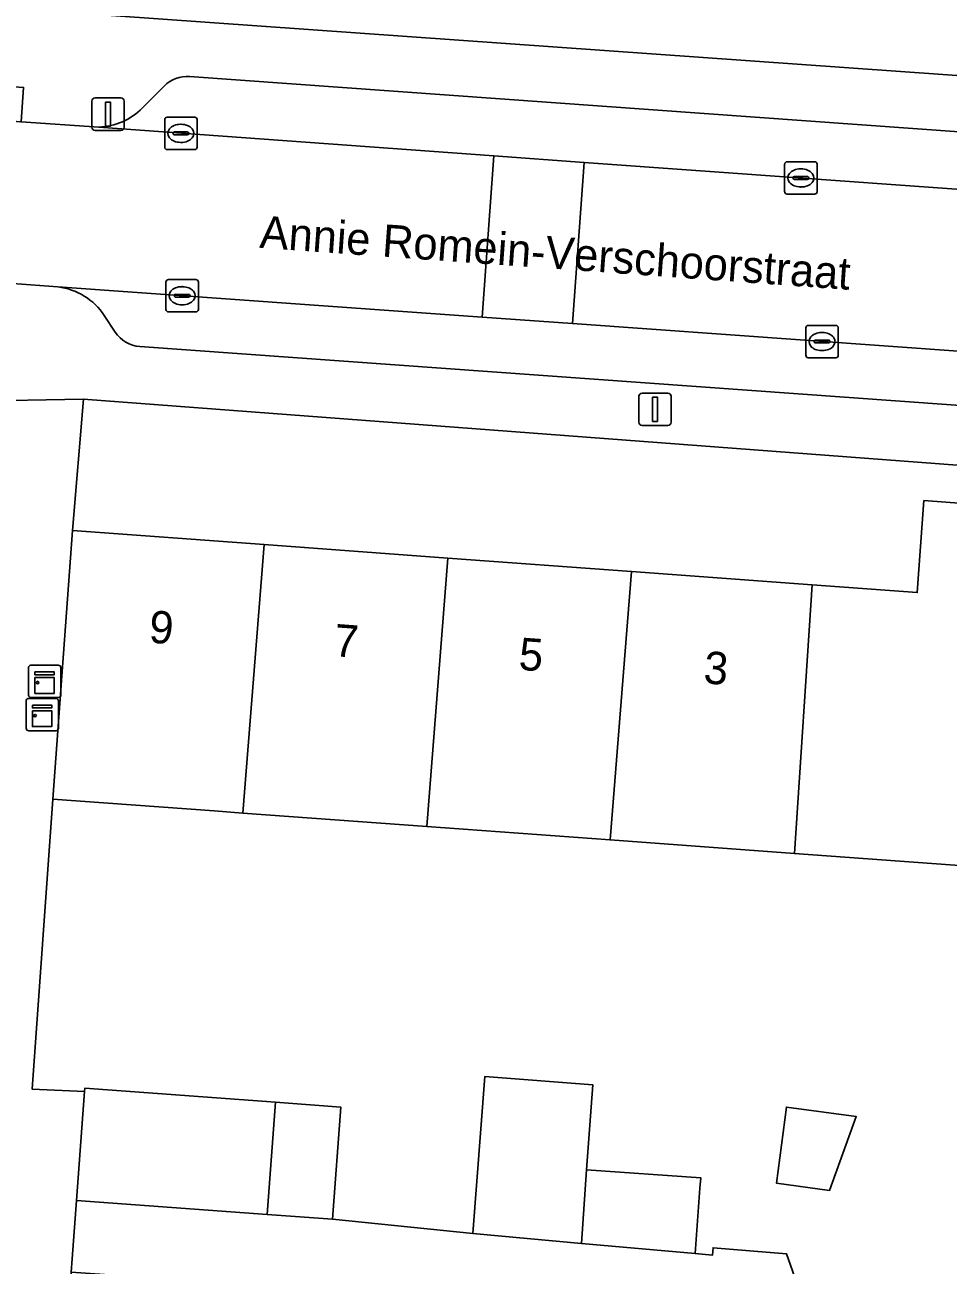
# Model space of a CAD drawing. Extents: x 160304 to 160955, y 383684 to 384161.
# Drawn here: x 160524.56 to 160553.09, y 383999.81 to 384038.14 of the extents above; entities that cross this region are included whole.
import ezdxf

# ---------------------------------------------------------------- set-up
doc = ezdxf.new("R2010")
doc.units = 0
for name, color, linetype in [('IMGEO_Erf', 7, 'Continuous'), ('IMGEO_Kast', 7, 'Continuous'), ('IMGEO_Kolk', 7, 'Continuous'), ('IMGEO_Lichtmast', 7, 'Continuous'), ('IMGEO_Muur', 7, 'Continuous'), ('IMGEO_Openbare_ruimte_label', 7, 'Continuous'), ('IMGEO_Pand', 7, 'Continuous'), ('IMGEO_Pand_nummerreeks', 7, 'Continuous'), ('IMGEO_Parkeervlak_open', 7, 'Continuous'), ('IMGEO_Rijbaan_lokaal_open', 7, 'Continuous'), ('IMGEO_Voetpad_open', 7, 'Continuous')]:
    doc.layers.add(name, color=color, linetype=linetype)

msp = doc.modelspace()

# ---------------------------------------------------------------- linework, layer by layer
at = {"layer": 'IMGEO_Erf'}
for points in [[(160575.545, 384053.821), (160571.219, 384050.086), (160566.909, 384046.364), (160559.815, 384040.236), (160550.457, 384040.871), (160544.77, 384041.284), (160539.067, 384041.697), (160533.4, 384042.108), (160527.543, 384042.533), (160527.234, 384038.426), (160562.223, 384035.951), (160577.428, 384049.127)], [(160596.174, 383986.448), (160584.428, 384000), (160576.873, 384008.716), (160576.438, 384011.974), (160567.161, 384022.807), (160563.188, 384023.793), (160526.375, 384026.574), (160526.037, 384022.511), (160531.953, 384022.076), (160537.633, 384021.659), (160543.309, 384021.242), (160548.888, 384020.833), (160552.137, 384020.594), (160552.345, 384023.437), (160555.755, 384023.187), (160558.392, 384020.13), (160564.484, 384013.069), (160568.208, 384008.753), (160571.874, 384004.582), (160574.541, 384006.884), (160578.378, 384002.452), (160580.501, 384000), (160582.098, 383998.155)], [(160554.286, 384012.093), (160548.348, 384012.529), (160542.649, 384012.948), (160536.981, 384013.365), (160531.302, 384013.782), (160530.415, 384013.847), (160525.428, 384014.213), (160524.792, 384005.245), (160526.404, 384005.17), (160526.412, 384005.276), (160532.305, 384004.843), (160534.327, 384004.694), (160534.073, 384001.224), (160538.402, 384000.781), (160538.777, 384005.639), (160542.11, 384005.382), (160541.923, 384002.758), (160545.446, 384002.508), (160545.423, 384002.185), (160545.279, 384000.164), (160545.808, 384000.116), (160545.829, 384000.347), (160548.095, 384000.159), (160549.241, 383996.917)]]:
    msp.add_lwpolyline(points, dxfattribs=at)
msp.add_lwpolyline([(160549.422, 384002.12), (160547.788, 384002.344), (160548.094, 384004.693), (160550.253, 384004.398)], close=True, dxfattribs=at)
at = {"layer": 'IMGEO_Kast'}
for p, q in [((160524.677, 384017.425), (160524.677, 384018.266)), ((160524.677, 384018.266), (160524.677, 384017.425)), ((160524.752, 384018.35), (160525.593, 384018.35)), ((160525.593, 384018.35), (160524.752, 384018.35)), ((160525.677, 384018.275), (160525.677, 384017.434)), ((160525.677, 384017.434), (160525.677, 384018.275)), ((160524.602, 384016.4), (160524.602, 384017.241)), ((160524.602, 384017.241), (160524.602, 384016.4)), ((160524.677, 384017.325), (160525.518, 384017.325)), ((160525.518, 384017.325), (160524.677, 384017.325)), ((160525.602, 384017.35), (160524.761, 384017.35)), ((160524.761, 384017.35), (160525.602, 384017.35)), ((160525.602, 384017.25), (160525.602, 384016.409)), ((160525.602, 384016.409), (160525.602, 384017.25)), ((160525.527, 384016.325), (160524.686, 384016.325)), ((160524.686, 384016.325), (160525.527, 384016.325))]:
    msp.add_line(p, q, dxfattribs=at)
for points in [[(160524.872, 384018.14), (160525.472, 384018.14), (160525.472, 384018.055), (160524.872, 384018.055), (160524.872, 384018.14)], [(160524.872, 384017.965), (160525.472, 384017.965), (160525.472, 384017.476), (160524.872, 384017.476), (160524.872, 384017.965)], [(160524.797, 384017.115), (160525.397, 384017.115), (160525.397, 384017.03), (160524.797, 384017.03), (160524.797, 384017.115)], [(160524.797, 384016.94), (160525.397, 384016.94), (160525.397, 384016.451), (160524.797, 384016.451), (160524.797, 384016.94)]]:
    msp.add_lwpolyline(points, dxfattribs=at)
for centre in [(160524.956, 384017.814), (160524.881, 384016.789)]:
    msp.add_circle(centre, 0.0377, dxfattribs=at)
for centre, start, end in [((160524.755, 384018.272), 92.4484, 184.2845), ((160524.755, 384018.272), 92.4484, 184.2845), ((160525.599, 384018.272), 2.4484, 94.2845), ((160525.599, 384018.272), 2.4484, 94.2845), ((160524.68, 384017.247), 92.4484, 184.2845), ((160524.68, 384017.247), 92.4484, 184.2845), ((160524.755, 384017.428), 182.4484, 274.2845), ((160524.755, 384017.428), 182.4484, 274.2845), ((160525.524, 384017.247), 2.4484, 94.2845), ((160525.524, 384017.247), 2.4484, 94.2845), ((160525.599, 384017.428), 272.4484, 4.2845), ((160525.599, 384017.428), 272.4484, 4.2845), ((160524.68, 384016.403), 182.4484, 274.2845), ((160524.68, 384016.403), 182.4484, 274.2845), ((160525.524, 384016.403), 272.4484, 4.2845), ((160525.524, 384016.403), 272.4484, 4.2845)]:
    msp.add_arc(centre, 0.0779, start, end, dxfattribs=at)
at = {"layer": 'IMGEO_Kolk'}
for p, q in [((160528.884, 384034.361), (160528.884, 384035.213)), ((160528.959, 384035.287), (160529.811, 384035.287)), ((160529.885, 384035.213), (160529.885, 384034.361)), ((160529.143, 384034.781), (160529.143, 384034.793)), ((160529.581, 384034.744), (160529.183, 384034.744)), ((160529.186, 384034.83), (160529.584, 384034.83)), ((160529.372, 384035.067), (160529.397, 384035.067)), ((160529.627, 384034.793), (160529.627, 384034.781)), ((160529.395, 384034.507), (160529.37, 384034.507)), ((160529.811, 384034.287), (160528.959, 384034.287)), ((160548.041, 384032.983), (160548.041, 384033.835)), ((160548.116, 384033.909), (160548.968, 384033.909)), ((160548.529, 384033.689), (160548.554, 384033.689)), ((160549.042, 384033.835), (160549.042, 384032.983)), ((160548.3, 384033.403), (160548.3, 384033.415)), ((160548.738, 384033.366), (160548.34, 384033.366)), ((160548.343, 384033.452), (160548.741, 384033.452)), ((160548.784, 384033.415), (160548.784, 384033.403)), ((160548.968, 384032.909), (160548.116, 384032.909)), ((160548.552, 384033.129), (160548.527, 384033.129)), ((160528.924, 384029.343), (160528.924, 384030.195)), ((160528.999, 384030.269), (160529.851, 384030.269)), ((160529.925, 384030.195), (160529.925, 384029.343)), ((160529.183, 384029.763), (160529.183, 384029.775)), ((160529.621, 384029.726), (160529.223, 384029.726)), ((160529.226, 384029.812), (160529.624, 384029.812)), ((160529.412, 384030.049), (160529.437, 384030.049)), ((160529.667, 384029.775), (160529.667, 384029.763)), ((160529.435, 384029.489), (160529.41, 384029.489)), ((160529.851, 384029.269), (160528.999, 384029.269)), ((160548.695, 384027.927), (160548.695, 384028.779)), ((160548.77, 384028.853), (160549.622, 384028.853)), ((160549.183, 384028.633), (160549.208, 384028.633)), ((160549.696, 384028.779), (160549.696, 384027.927)), ((160548.954, 384028.347), (160548.954, 384028.359)), ((160549.392, 384028.31), (160548.994, 384028.31)), ((160548.997, 384028.396), (160549.395, 384028.396)), ((160549.438, 384028.359), (160549.438, 384028.347)), ((160549.622, 384027.853), (160548.77, 384027.853)), ((160549.206, 384028.073), (160549.181, 384028.073))]:
    msp.add_line(p, q, dxfattribs=at)
for points in [[(160528.884, 384034.361), (160528.884, 384035.213)], [(160528.959, 384035.287), (160529.811, 384035.287)], [(160529.885, 384035.213), (160529.885, 384034.361)], [(160529.811, 384034.287), (160528.959, 384034.287)], [(160548.041, 384032.983), (160548.041, 384033.835)], [(160548.116, 384033.909), (160548.968, 384033.909)], [(160549.042, 384033.835), (160549.042, 384032.983)], [(160548.968, 384032.909), (160548.116, 384032.909)], [(160528.924, 384029.343), (160528.924, 384030.195)], [(160528.999, 384030.269), (160529.851, 384030.269)], [(160529.925, 384030.195), (160529.925, 384029.343)], [(160529.851, 384029.269), (160528.999, 384029.269)], [(160548.695, 384027.927), (160548.695, 384028.779)], [(160548.77, 384028.853), (160549.622, 384028.853)], [(160549.696, 384028.779), (160549.696, 384027.927)], [(160549.622, 384027.853), (160548.77, 384027.853)]]:
    msp.add_lwpolyline(points, dxfattribs=at)
for centre, radius, start, end in [((160528.961, 384035.211), 0.0765, 91.552, 178.448), ((160528.961, 384035.211), 0.0765, 91.552, 178.448), ((160529.809, 384035.211), 0.0765, 1.552, 88.448), ((160529.809, 384035.211), 0.0765, 1.552, 88.448), ((160529.183, 384034.79), 0.0403, 85.8775, 175.7526), ((160529.18, 384034.78), 0.0366, 178.938, 274.7102), ((160529.584, 384034.787), 0.043, 264.8664, 352.4533), ((160529.588, 384034.792), 0.0386, 1.7309, 96.639), ((160528.961, 384034.363), 0.0765, 181.552, 268.448), ((160528.961, 384034.363), 0.0765, 181.552, 268.448), ((160529.809, 384034.363), 0.0765, 271.552, 358.448), ((160529.809, 384034.363), 0.0765, 271.552, 358.448), ((160548.118, 384033.833), 0.0765, 91.552, 178.448), ((160548.118, 384033.833), 0.0765, 91.552, 178.448), ((160548.966, 384033.833), 0.0765, 1.552, 88.448), ((160548.966, 384033.833), 0.0765, 1.552, 88.448), ((160548.34, 384033.412), 0.0403, 85.8775, 175.7526), ((160548.337, 384033.402), 0.0366, 178.938, 274.7102), ((160548.741, 384033.409), 0.043, 264.8664, 352.4533), ((160548.745, 384033.414), 0.0386, 1.7309, 96.639), ((160548.118, 384032.985), 0.0765, 181.552, 268.448), ((160548.118, 384032.985), 0.0765, 181.552, 268.448), ((160548.966, 384032.985), 0.0765, 271.552, 358.448), ((160548.966, 384032.985), 0.0765, 271.552, 358.448), ((160529.001, 384030.193), 0.0765, 91.552, 178.448), ((160529.001, 384030.193), 0.0765, 91.552, 178.448), ((160529.849, 384030.193), 0.0765, 1.552, 88.448), ((160529.849, 384030.193), 0.0765, 1.552, 88.448), ((160529.223, 384029.772), 0.0403, 85.8775, 175.7526), ((160529.22, 384029.762), 0.0366, 178.938, 274.7102), ((160529.624, 384029.769), 0.043, 264.8664, 352.4533), ((160529.628, 384029.774), 0.0386, 1.7309, 96.639), ((160529.001, 384029.345), 0.0765, 181.552, 268.448), ((160529.001, 384029.345), 0.0765, 181.552, 268.448), ((160529.849, 384029.345), 0.0765, 271.552, 358.448), ((160529.849, 384029.345), 0.0765, 271.552, 358.448), ((160548.772, 384028.777), 0.0765, 91.552, 178.448), ((160548.772, 384028.777), 0.0765, 91.552, 178.448), ((160549.62, 384028.777), 0.0765, 1.552, 88.448), ((160549.62, 384028.777), 0.0765, 1.552, 88.448), ((160548.994, 384028.356), 0.0403, 85.8775, 175.7526), ((160548.991, 384028.346), 0.0366, 178.938, 274.7102), ((160549.395, 384028.353), 0.043, 264.8664, 352.4533), ((160549.399, 384028.358), 0.0386, 1.7309, 96.639), ((160548.772, 384027.929), 0.0765, 181.552, 268.448), ((160548.772, 384027.929), 0.0765, 181.552, 268.448), ((160549.62, 384027.929), 0.0765, 271.552, 358.448), ((160549.62, 384027.929), 0.0765, 271.552, 358.448)]:
    msp.add_arc(centre, radius, start, end, dxfattribs=at)
for centre, major_axis, ratio, start_param, end_param in [((160529.371, 384034.787), (-0.387, 0.002), 0.722429, 4.712389, 7.853982), ((160529.396, 384034.787), (-0.39, 0.002), 0.717154, 1.570796, 4.712389), ((160548.528, 384033.409), (-0.387, 0.002), 0.722429, 4.712389, 7.853982), ((160548.553, 384033.409), (-0.39, 0.002), 0.717154, 1.570796, 4.712389), ((160529.411, 384029.769), (-0.387, 0.002), 0.722429, 4.712389, 7.853982), ((160529.436, 384029.769), (-0.39, 0.002), 0.717154, 1.570796, 4.712389), ((160549.182, 384028.353), (-0.387, 0.002), 0.722429, 4.712389, 7.853982), ((160549.207, 384028.353), (-0.39, 0.002), 0.717154, 1.570796, 4.712389)]:
    msp.add_ellipse(centre, major_axis=major_axis, ratio=ratio, start_param=start_param, end_param=end_param, dxfattribs=at)
at = {"layer": 'IMGEO_Lichtmast'}
for p, q in [((160526.738, 384035.88), (160527.528, 384035.88)), ((160527.528, 384035.88), (160526.738, 384035.88)), ((160526.638, 384034.98), (160526.638, 384035.78)), ((160526.638, 384035.78), (160526.638, 384034.98)), ((160527.628, 384035.78), (160527.628, 384034.98)), ((160527.628, 384034.98), (160527.628, 384035.78)), ((160527.528, 384034.88), (160526.738, 384034.88)), ((160526.738, 384034.88), (160527.528, 384034.88)), ((160543.54, 384025.86), (160543.54, 384026.66)), ((160543.54, 384026.66), (160543.54, 384025.86)), ((160543.64, 384026.76), (160544.43, 384026.76)), ((160544.43, 384026.76), (160543.64, 384026.76)), ((160544.53, 384026.66), (160544.53, 384025.86)), ((160544.53, 384025.86), (160544.53, 384026.66)), ((160544.43, 384025.76), (160543.64, 384025.76)), ((160543.64, 384025.76), (160544.43, 384025.76))]:
    msp.add_line(p, q, dxfattribs=at)
for points in [[(160527.058, 384035.755), (160527.208, 384035.755), (160527.208, 384035.005), (160527.058, 384035.005), (160527.058, 384035.755)], [(160543.96, 384026.635), (160544.11, 384026.635), (160544.11, 384025.885), (160543.96, 384025.885), (160543.96, 384026.635)]]:
    msp.add_lwpolyline(points, dxfattribs=at)
for centre, start, end in [((160526.738, 384035.78), 90, 180), ((160526.738, 384035.78), 90, 180), ((160527.528, 384035.78), 0, 90), ((160527.528, 384035.78), 360, 90), ((160526.738, 384034.98), 180, 270), ((160526.738, 384034.98), 180, 270), ((160527.528, 384034.98), 270, 0), ((160527.528, 384034.98), 270, 0), ((160543.64, 384026.66), 90, 180), ((160543.64, 384026.66), 90, 180), ((160544.43, 384026.66), 0, 90), ((160544.43, 384026.66), 360, 90), ((160543.64, 384025.86), 180, 270), ((160543.64, 384025.86), 180, 270), ((160544.43, 384025.86), 270, 0), ((160544.43, 384025.86), 270, 0)]:
    msp.add_arc(centre, 0.1, start, end, dxfattribs=at)
at = {"layer": 'IMGEO_Muur'}
msp.add_lwpolyline([(160525.428, 384014.213), (160524.792, 384005.245), (160526.404, 384005.17)], dxfattribs=at)
at = {"layer": 'IMGEO_Pand'}
for points in [[(160548.888, 384020.833), (160548.348, 384012.529), (160554.286, 384012.093), (160558.392, 384020.13), (160555.755, 384023.187), (160552.345, 384023.437), (160552.137, 384020.594)], [(160531.953, 384022.076), (160526.037, 384022.511), (160525.428, 384014.213), (160530.415, 384013.847), (160531.302, 384013.782)], [(160531.302, 384013.782), (160536.981, 384013.365), (160537.633, 384021.659), (160531.953, 384022.076)], [(160537.633, 384021.659), (160536.981, 384013.365), (160542.649, 384012.948), (160543.309, 384021.242)], [(160548.888, 384020.833), (160543.309, 384021.242), (160542.649, 384012.948), (160548.348, 384012.529)], [(160538.402, 384000.781), (160541.761, 384000.478), (160541.923, 384002.758), (160542.11, 384005.382), (160538.777, 384005.639)], [(160532.305, 384004.843), (160526.412, 384005.276), (160526.404, 384005.17), (160526.157, 384001.805), (160532.054, 384001.372)], [(160532.305, 384004.843), (160532.054, 384001.372), (160534.073, 384001.224), (160534.327, 384004.694)], [(160547.788, 384002.344), (160549.422, 384002.12), (160550.253, 384004.398), (160548.094, 384004.693)], [(160541.923, 384002.758), (160541.761, 384000.478), (160545.279, 384000.164), (160545.423, 384002.185), (160545.446, 384002.508)]]:
    msp.add_lwpolyline(points, close=True, dxfattribs=at)
at = {"layer": 'IMGEO_Parkeervlak_open'}
for points in [[(160528.875, 384036.254), (160528.191, 384035.568)], [(160556.726, 384034.597), (160529.655, 384036.545)], [(160526.85, 384034.98), (160539.053, 384034.09), (160541.846, 384033.889), (160559.384, 384032.627)], [(160570.205, 384026.85), (160541.488, 384028.906), (160538.695, 384029.106), (160525.582, 384030.043)], [(160527.019, 384029.157), (160527.357, 384028.645)], [(160528.12, 384028.197), (160567.23, 384025.383)]]:
    msp.add_lwpolyline(points, dxfattribs=at)
for centre, radius, start, end in [((160529.581, 384035.553), 0.995, 85.7193, 135.1995), ((160526.772, 384036.981), 2.003, 272.237, 315.1159), ((160525.35, 384028.058), 1.998, 33.3556, 83.3316), ((160528.192, 384029.193), 0.999, 213.2869, 265.874)]:
    msp.add_arc(centre, radius, start, end, dxfattribs=at)
at = {"layer": 'IMGEO_Rijbaan_lokaal_open'}
for points in [[(160485.518, 384032.958), (160485.696, 384032.933), (160485.869, 384032.893), (160486.042, 384032.836), (160500, 384031.877), (160518.132, 384030.575), (160519.523, 384030.479), (160523.351, 384030.205), (160525.582, 384030.043), (160538.695, 384029.106), (160539.053, 384034.09), (160526.85, 384034.98), (160524.445, 384035.141), (160519.567, 384035.492), (160518.166, 384035.63), (160500, 384036.9), (160486.967, 384037.844), (160486.676, 384037.858)], [(160587.027, 384029.795), (160577.386, 384032.36), (160576.04, 384031.792), (160574.287, 384031.555), (160563.316, 384032.344), (160561.983, 384032.44), (160559.384, 384032.627), (160541.846, 384033.889), (160541.488, 384028.906), (160570.205, 384026.85), (160572.921, 384026.655), (160575.533, 384026.468)]]:
    msp.add_lwpolyline(points, dxfattribs=at)
msp.add_lwpolyline([(160538.695, 384029.106), (160541.488, 384028.906), (160541.846, 384033.889), (160539.053, 384034.09)], close=True, dxfattribs=at)
at = {"layer": 'IMGEO_Voetpad_open'}
for points in [[(160562.223, 384035.951), (160527.234, 384038.426), (160523.822, 384038.679), (160520.333, 384038.909), (160518.569, 384038.999), (160500, 384040.365), (160485.928, 384041.4)], [(160518.166, 384035.63), (160519.567, 384035.492), (160519.644, 384036.56), (160524.522, 384036.209), (160524.445, 384035.141), (160526.85, 384034.98)], [(160528.191, 384035.568), (160528.875, 384036.254)], [(160529.655, 384036.545), (160556.726, 384034.597)], [(160525.582, 384030.043), (160523.351, 384030.205), (160523.314, 384029.707), (160521.414, 384029.843), (160521.202, 384026.61), (160522.919, 384026.511), (160526.375, 384026.574), (160563.188, 384023.793), (160567.161, 384022.807), (160572.716, 384022.448), (160572.921, 384026.655)], [(160527.357, 384028.645), (160527.019, 384029.157)], [(160567.23, 384025.383), (160528.12, 384028.197)], [(160518.776, 383947.168), (160518.729, 383946.518), (160519.227, 383946.483), (160518.953, 383942.703), (160518.455, 383942.738), (160517.105, 383924.059), (160518.927, 383923.923), (160519.059, 383925.551), (160519.677, 383933.96), (160519.798, 383935.598), (160519.906, 383937.041), (160520.34, 383942.858), (160520.599, 383946.385), (160522.16, 383946.27), (160522.302, 383948.238), (160525.998, 383999.592), (160526.027, 384000), (160526.157, 384001.805), (160526.404, 384005.17), (160524.792, 384005.245), (160525.428, 384014.213), (160526.037, 384022.511), (160526.375, 384026.574)], [(160526.375, 384026.574), (160522.919, 384026.511), (160522.798, 384024.566)]]:
    msp.add_lwpolyline(points, dxfattribs=at)
msp.add_lwpolyline([(160541.761, 384000.478), (160538.402, 384000.781), (160534.073, 384001.224), (160532.054, 384001.372), (160526.157, 384001.805), (160526.027, 384000), (160525.998, 383999.592), (160528.645, 383999.401), (160533.632, 383999.034), (160536.928, 383998.791), (160547.178, 383998.146), (160547.25, 383997.975), (160547.877, 383996.497), (160549.217, 383993.34), (160550.415, 383989.625), (160551.619, 383986.228), (160553.065, 383986.723), (160551.866, 383990.106), (160550.43, 383993.501), (160549.241, 383996.917), (160548.095, 384000.159), (160545.829, 384000.347), (160545.808, 384000.116), (160545.279, 384000.164)], close=True, dxfattribs=at)
for centre, radius, start, end in [((160529.581, 384035.553), 0.995, 85.7193, 135.1995), ((160526.772, 384036.981), 2.003, 272.237, 315.1159), ((160525.35, 384028.058), 1.998, 33.3556, 83.3316), ((160528.192, 384029.193), 0.999, 213.2869, 265.874)]:
    msp.add_arc(centre, radius, start, end, dxfattribs=at)

# ---------------------------------------------------------------- texts
at = {"layer": 'IMGEO_Openbare_ruimte_label'}
msp.add_text('Annie Romein-Verschoorstraat', height=1, rotation=355.9266, dxfattribs=at).set_placement((160531.798, 384031.252))
at = {"layer": 'IMGEO_Pand_nummerreeks'}
for s, p in [('9', (160528.378, 384019.05)), ('7', (160534.091, 384018.631)), ('5', (160539.803, 384018.211)), ('3', (160545.516, 384017.792))]:
    msp.add_text(s, height=1, rotation=355.8002, dxfattribs=at).set_placement(p)

doc.saveas('drawing.dxf')
